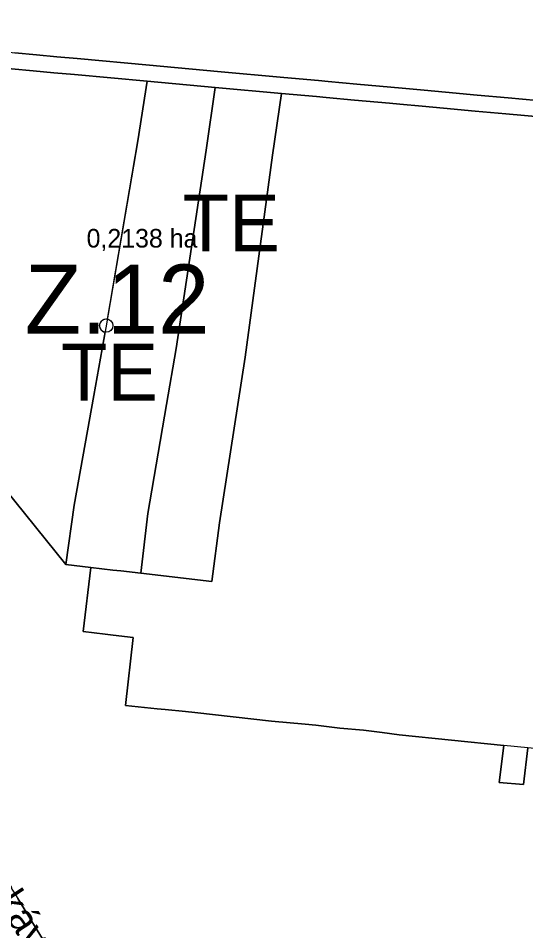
# Model space of a CAD drawing. Extents: x -555509 to -553005, y -1186756 to -1182560.
# Drawn here: x -554451.9 to -554326.9, y -1184312.3 to -1184087.6 of the extents above; entities that cross this region are included whole.
import ezdxf

# ---------------------------------------------------------------- set-up
doc = ezdxf.new("R2010")
doc.units = 0
for name, color, linetype in [('Level 15', 7, 'Continuous'), ('Level 26', 7, 'Continuous'), ('Level 29', 7, 'Continuous'), ('Level 36', 7, 'Continuous'), ('Level 4', 7, 'Continuous'), ('Level 46', 7, 'Continuous'), ('Level 52', 7, 'Continuous'), ('Level 56', 7, 'Continuous'), ('Level 57', 7, 'Continuous'), ('Level 59', 7, 'Continuous'), ('Level 6', 7, 'Continuous'), ('Level 63', 7, 'Continuous'), ('navrh_TE', 7, 'Continuous'), ('OBRYS_PLOCH', 7, 'Continuous'), ('stav_AP', 7, 'Continuous'), ('stav_BV', 7, 'Continuous'), ('stav_PU', 7, 'Continuous'), ('stav_TE', 7, 'Continuous'), ('stav_ZZ', 7, 'Continuous')]:
    doc.layers.add(name, color=color, linetype=linetype)

msp = doc.modelspace()

# ---------------------------------------------------------------- linework, layer by layer
at = {"layer": 'Level 15'}
msp.add_lwpolyline([(-554445.21, -1184315.42), (-554448.55, -1184310.07), (-554449.49, -1184308.45), (-554452.02, -1184304.43)], dxfattribs=at)
at = {"layer": 'Level 26'}
for p, q in [((-554448.17, -1184100.51), (-554443.1, -1184100.97)), ((-554376.06, -1184107.07), (-554369.02, -1184107.71)), ((-554369.02, -1184107.71), (-554360.47, -1184108.49)), ((-554331.76, -1184111.1), (-554321.21, -1184112.07))]:
    msp.add_line(p, q, dxfattribs=at)
for points in [[(-554368.51, -1184103.78), (-554375.53, -1184103.14), (-554377.89, -1184102.92), (-554386.44, -1184102.14), (-554402.8, -1184100.65), (-554419.51, -1184099.13), (-554437.34, -1184097.5), (-554442.37, -1184097.04), (-554447.41, -1184096.58), (-554452.71, -1184096.1)], [(-554464.64, -1184098.73), (-554453.5, -1184100.02), (-554448.17, -1184100.51)], [(-554443.1, -1184100.97), (-554438.03, -1184101.43), (-554420.12, -1184103.06), (-554403.37, -1184104.58), (-554387.01, -1184106.07), (-554378.42, -1184106.86), (-554376.06, -1184107.07)], [(-554165.91, -1184122.25), (-554184.57, -1184120.55), (-554194.22, -1184119.67), (-554204.27, -1184118.75), (-554209.96, -1184118.23), (-554215.7, -1184117.71), (-554222.5, -1184117.09), (-554230.67, -1184116.35), (-554238.72, -1184115.61), (-554251.02, -1184114.49), (-554269.76, -1184112.78), (-554288.18, -1184111.1), (-554294.43, -1184110.53), (-554300.68, -1184109.96), (-554310.42, -1184109.07), (-554315.86, -1184108.58), (-554320.66, -1184108.14), (-554331.2, -1184107.18), (-554338.84, -1184106.48), (-554346.65, -1184105.77), (-554351.87, -1184105.29), (-554357.35, -1184104.79), (-554368.51, -1184103.78)], [(-554360.47, -1184108.49), (-554357.89, -1184108.73), (-554352.39, -1184109.23)], [(-554352.39, -1184109.23), (-554347.18, -1184109.7), (-554339.38, -1184110.41), (-554331.76, -1184111.1)]]:
    msp.add_lwpolyline(points, dxfattribs=at)
at = {"layer": 'Level 36'}
msp.add_line((-554434.03, -1184222.84), (-554440.16, -1184222.12), dxfattribs=at)
for points in [[(-554440.16, -1184222.12), (-554492.51, -1184157.13), (-554513.37, -1184150.34), (-554518.87, -1184169.02), (-554521.24, -1184177.54), (-554523.13, -1184182.45), (-554525.77, -1184189.28)], [(-554283.1, -1184235.02), (-554284, -1184242.55), (-554283.44, -1184250.8), (-554287.72, -1184271.23), (-554326.33, -1184267.32), (-554332.24, -1184266.72), (-554358.07, -1184264.1), (-554362.22, -1184263.55), (-554366.82, -1184262.94), (-554372.66, -1184262.44), (-554378.6, -1184261.72), (-554381.18, -1184261.48), (-554389.53, -1184260.75), (-554408.36, -1184258.58), (-554410.7, -1184258.35), (-554415.69, -1184257.85), (-554417.69, -1184257.65), (-554425.5, -1184256.87), (-554423.54, -1184240.08), (-554428.47, -1184239.51), (-554430.45, -1184239.27), (-554435.88, -1184238.64), (-554434.03, -1184222.84)]]:
    msp.add_lwpolyline(points, dxfattribs=at)
at = {"layer": 'Level 4'}
msp.add_circle((-554430.21, -1184163.28), 1.64, dxfattribs=at)
at = {"layer": 'Level 52'}
for points in [[(-554419.97, -1184209.57), (-554421.69, -1184224.28), (-554404.2, -1184226.28), (-554402.34, -1184211.82), (-554397.8, -1184182.71), (-554395.98, -1184171.07), (-554389.22, -1184121.26), (-554387.01, -1184106.07), (-554403.37, -1184104.58), (-554405.62, -1184120.08), (-554413.02, -1184168.92), (-554415.38, -1184182.72), (-554419.97, -1184209.57)], [(-554326.33, -1184267.32), (-554327.43, -1184276.33), (-554333.44, -1184275.83), (-554332.24, -1184266.72), (-554358.07, -1184264.1), (-554362.22, -1184263.55), (-554366.82, -1184262.94), (-554372.66, -1184262.44), (-554378.6, -1184261.72), (-554381.18, -1184261.48), (-554389.53, -1184260.75), (-554408.36, -1184258.58), (-554410.7, -1184258.35), (-554415.69, -1184257.85), (-554417.69, -1184257.65), (-554425.5, -1184256.87), (-554423.54, -1184240.08), (-554428.47, -1184239.51), (-554430.45, -1184239.27), (-554435.88, -1184238.64), (-554434.03, -1184222.84), (-554440.16, -1184222.12), (-554492.51, -1184157.13)]]:
    msp.add_lwpolyline(points, dxfattribs=at)
at = {"layer": 'Level 56'}
for p, q in [((-554403.37, -1184104.58), (-554420.12, -1184103.06)), ((-554405.62, -1184120.08), (-554403.37, -1184104.58)), ((-554413.02, -1184168.92), (-554405.62, -1184120.08)), ((-554415.38, -1184182.72), (-554413.02, -1184168.92)), ((-554419.97, -1184209.57), (-554415.38, -1184182.72)), ((-554421.69, -1184224.28), (-554419.97, -1184209.57)), ((-554434.03, -1184222.84), (-554428.6, -1184223.48)), ((-554428.6, -1184223.48), (-554426.63, -1184223.71)), ((-554426.63, -1184223.71), (-554421.69, -1184224.28))]:
    msp.add_line(p, q, dxfattribs=at)
msp.add_lwpolyline([(-554420.12, -1184103.06), (-554422.41, -1184117.71), (-554430.77, -1184166.73), (-554433.24, -1184180.51), (-554438.09, -1184207.49), (-554440.16, -1184222.12), (-554434.03, -1184222.84)], dxfattribs=at)
at = {"layer": 'Level 6'}
msp.add_lwpolyline([(-554326.33, -1184267.32), (-554327.43, -1184276.33), (-554333.44, -1184275.83), (-554332.24, -1184266.72), (-554358.07, -1184264.1), (-554362.22, -1184263.55), (-554366.82, -1184262.94), (-554372.66, -1184262.44), (-554378.6, -1184261.72), (-554381.18, -1184261.48), (-554389.53, -1184260.75), (-554408.36, -1184258.58), (-554410.7, -1184258.35), (-554415.69, -1184257.85), (-554417.69, -1184257.65), (-554425.5, -1184256.87), (-554423.54, -1184240.08), (-554428.47, -1184239.51), (-554430.45, -1184239.27), (-554435.88, -1184238.64), (-554434.03, -1184222.84), (-554440.16, -1184222.12), (-554492.51, -1184157.13)], dxfattribs=at)
at = {"layer": 'navrh_TE'}
for p, q in [((-554403.37, -1184104.58), (-554420.12, -1184103.06)), ((-554403.37, -1184104.58), (-554420.12, -1184103.06)), ((-554405.62, -1184120.08), (-554403.37, -1184104.58)), ((-554405.62, -1184120.08), (-554403.37, -1184104.58)), ((-554413.02, -1184168.92), (-554405.62, -1184120.08)), ((-554413.02, -1184168.92), (-554405.62, -1184120.08)), ((-554415.38, -1184182.72), (-554413.02, -1184168.92)), ((-554415.38, -1184182.72), (-554413.02, -1184168.92)), ((-554419.97, -1184209.57), (-554415.38, -1184182.72)), ((-554419.97, -1184209.57), (-554415.38, -1184182.72)), ((-554421.69, -1184224.28), (-554419.97, -1184209.57)), ((-554421.69, -1184224.28), (-554419.97, -1184209.57)), ((-554434.03, -1184222.84), (-554428.6, -1184223.48)), ((-554434.03, -1184222.84), (-554428.6, -1184223.48)), ((-554428.6, -1184223.48), (-554426.63, -1184223.71)), ((-554428.6, -1184223.48), (-554426.63, -1184223.71)), ((-554426.63, -1184223.71), (-554421.69, -1184224.28)), ((-554426.63, -1184223.71), (-554421.69, -1184224.28))]:
    msp.add_line(p, q, dxfattribs=at)
msp.add_lwpolyline([(-554420.12, -1184103.06), (-554422.41, -1184117.71), (-554430.77, -1184166.73), (-554433.24, -1184180.51), (-554438.09, -1184207.49), (-554440.16, -1184222.12), (-554434.03, -1184222.84)], dxfattribs=at)
msp.add_lwpolyline([(-554420.12, -1184103.06), (-554422.41, -1184117.71), (-554430.77, -1184166.73), (-554433.24, -1184180.51), (-554438.09, -1184207.49), (-554440.16, -1184222.12), (-554434.03, -1184222.84)], dxfattribs=at)
at = {"layer": 'OBRYS_PLOCH'}
for p, q in [((-554448.17, -1184100.51), (-554443.1, -1184100.97)), ((-554403.37, -1184104.58), (-554420.12, -1184103.06)), ((-554405.62, -1184120.08), (-554403.37, -1184104.58)), ((-554387.01, -1184106.07), (-554389.22, -1184121.26)), ((-554376.06, -1184107.07), (-554369.02, -1184107.71)), ((-554369.02, -1184107.71), (-554376.06, -1184107.07)), ((-554369.02, -1184107.71), (-554360.47, -1184108.49)), ((-554360.47, -1184108.49), (-554369.02, -1184107.71)), ((-554357.89, -1184108.73), (-554360.47, -1184108.49)), ((-554352.39, -1184109.23), (-554357.89, -1184108.73)), ((-554347.18, -1184109.7), (-554352.39, -1184109.23)), ((-554339.38, -1184110.41), (-554347.18, -1184109.7)), ((-554331.76, -1184111.1), (-554339.38, -1184110.41)), ((-554331.76, -1184111.1), (-554321.21, -1184112.07)), ((-554321.21, -1184112.07), (-554331.76, -1184111.1)), ((-554413.02, -1184168.92), (-554405.62, -1184120.08)), ((-554389.22, -1184121.26), (-554395.98, -1184171.07)), ((-554415.38, -1184182.72), (-554413.02, -1184168.92)), ((-554395.98, -1184171.07), (-554397.8, -1184182.71)), ((-554419.97, -1184209.57), (-554415.38, -1184182.72)), ((-554397.8, -1184182.71), (-554402.34, -1184211.82)), ((-554421.69, -1184224.28), (-554419.97, -1184209.57)), ((-554402.34, -1184211.82), (-554404.2, -1184226.28)), ((-554434.03, -1184222.84), (-554440.16, -1184222.12)), ((-554434.03, -1184222.84), (-554435.88, -1184238.64)), ((-554434.03, -1184222.84), (-554428.6, -1184223.48)), ((-554428.6, -1184223.48), (-554434.03, -1184222.84)), ((-554428.6, -1184223.48), (-554426.63, -1184223.71)), ((-554426.63, -1184223.71), (-554428.6, -1184223.48)), ((-554426.63, -1184223.71), (-554421.69, -1184224.28)), ((-554421.69, -1184224.28), (-554426.63, -1184223.71)), ((-554404.2, -1184226.28), (-554421.69, -1184224.28)), ((-554435.88, -1184238.64), (-554430.45, -1184239.27)), ((-554428.47, -1184239.51), (-554430.45, -1184239.27)), ((-554430.45, -1184239.27), (-554428.47, -1184239.51)), ((-554423.54, -1184240.08), (-554428.47, -1184239.51)), ((-554428.47, -1184239.51), (-554423.54, -1184240.08)), ((-554425.5, -1184256.87), (-554423.54, -1184240.08)), ((-554423.54, -1184240.08), (-554425.5, -1184256.87)), ((-554417.69, -1184257.65), (-554425.5, -1184256.87)), ((-554415.69, -1184257.85), (-554417.69, -1184257.65)), ((-554410.7, -1184258.35), (-554415.69, -1184257.85)), ((-554415.69, -1184257.85), (-554410.7, -1184258.35)), ((-554408.36, -1184258.58), (-554410.7, -1184258.35)), ((-554410.7, -1184258.35), (-554408.36, -1184258.58)), ((-554378.6, -1184261.72), (-554381.18, -1184261.48)), ((-554381.18, -1184261.48), (-554378.6, -1184261.72)), ((-554372.66, -1184262.44), (-554378.6, -1184261.72)), ((-554378.6, -1184261.72), (-554372.66, -1184262.44)), ((-554366.82, -1184262.94), (-554372.66, -1184262.44)), ((-554372.66, -1184262.44), (-554366.82, -1184262.94)), ((-554362.22, -1184263.55), (-554366.82, -1184262.94)), ((-554366.82, -1184262.94), (-554362.22, -1184263.55)), ((-554358.07, -1184264.1), (-554362.22, -1184263.55)), ((-554362.22, -1184263.55), (-554358.07, -1184264.1)), ((-554332.24, -1184266.72), (-554358.07, -1184264.1)), ((-554358.07, -1184264.1), (-554332.24, -1184266.72)), ((-554333.44, -1184275.83), (-554332.24, -1184266.72)), ((-554332.24, -1184266.72), (-554333.44, -1184275.83)), ((-554326.33, -1184267.32), (-554327.43, -1184276.33)), ((-554327.43, -1184276.33), (-554326.33, -1184267.32)), ((-554327.43, -1184276.33), (-554333.44, -1184275.83)), ((-554333.44, -1184275.83), (-554327.43, -1184276.33)), ((-554448.55, -1184310.07), (-554445.21, -1184315.42))]:
    msp.add_line(p, q, dxfattribs=at)
for points in [[(-554521.41, -1184087.55), (-554510.78, -1184088.88), (-554505.63, -1184089.52), (-554500.07, -1184090.21), (-554488.69, -1184091.62), (-554478.43, -1184092.9), (-554468.65, -1184094.12), (-554463.81, -1184094.72), (-554452.71, -1184096.1), (-554447.41, -1184096.58), (-554442.37, -1184097.04), (-554437.34, -1184097.5), (-554419.51, -1184099.13), (-554402.8, -1184100.65), (-554386.44, -1184102.14), (-554377.89, -1184102.92), (-554375.53, -1184103.14), (-554368.51, -1184103.78)], [(-554368.51, -1184103.78), (-554375.53, -1184103.14), (-554377.89, -1184102.92), (-554386.44, -1184102.14), (-554402.8, -1184100.65), (-554419.51, -1184099.13), (-554437.34, -1184097.5), (-554442.37, -1184097.04), (-554447.41, -1184096.58), (-554452.71, -1184096.1)], [(-554464.64, -1184098.73), (-554453.5, -1184100.02), (-554448.17, -1184100.51)], [(-554443.1, -1184100.97), (-554438.03, -1184101.43), (-554420.12, -1184103.06), (-554403.37, -1184104.58), (-554387.01, -1184106.07), (-554378.42, -1184106.86), (-554376.06, -1184107.07)], [(-554420.12, -1184103.06), (-554422.41, -1184117.71), (-554430.77, -1184166.73), (-554433.24, -1184180.51), (-554438.09, -1184207.49), (-554440.16, -1184222.12), (-554434.03, -1184222.84)], [(-554165.91, -1184122.25), (-554184.57, -1184120.55), (-554194.22, -1184119.67), (-554204.27, -1184118.75), (-554209.96, -1184118.23), (-554215.7, -1184117.71), (-554222.5, -1184117.09), (-554230.67, -1184116.35), (-554238.72, -1184115.61), (-554251.02, -1184114.49), (-554269.76, -1184112.78), (-554288.18, -1184111.1), (-554294.43, -1184110.53), (-554300.68, -1184109.96), (-554310.42, -1184109.07), (-554315.86, -1184108.58), (-554320.66, -1184108.14), (-554331.2, -1184107.18), (-554338.84, -1184106.48), (-554346.65, -1184105.77), (-554351.87, -1184105.29), (-554357.35, -1184104.79), (-554368.51, -1184103.78)], [(-554368.51, -1184103.78), (-554357.35, -1184104.79), (-554351.87, -1184105.29), (-554346.65, -1184105.77), (-554338.84, -1184106.48), (-554331.2, -1184107.18), (-554320.66, -1184108.14), (-554315.86, -1184108.58), (-554310.42, -1184109.07), (-554300.68, -1184109.96), (-554294.43, -1184110.53), (-554288.18, -1184111.1), (-554269.76, -1184112.78), (-554251.02, -1184114.49), (-554238.72, -1184115.61), (-554230.67, -1184116.35), (-554222.5, -1184117.09), (-554215.7, -1184117.71), (-554209.96, -1184118.23), (-554204.27, -1184118.75), (-554194.22, -1184119.67), (-554184.57, -1184120.55), (-554165.91, -1184122.25)], [(-554403.37, -1184104.58), (-554405.62, -1184120.08)], [(-554387.01, -1184106.07), (-554403.37, -1184104.58)], [(-554389.22, -1184121.26), (-554387.01, -1184106.07)], [(-554376.06, -1184107.07), (-554378.42, -1184106.86), (-554387.01, -1184106.07)], [(-554360.47, -1184108.49), (-554357.89, -1184108.73), (-554352.39, -1184109.23)], [(-554352.39, -1184109.23), (-554347.18, -1184109.7), (-554339.38, -1184110.41), (-554331.76, -1184111.1)], [(-554405.62, -1184120.08), (-554409.66, -1184146.74), (-554413.02, -1184168.92)], [(-554395.98, -1184171.07), (-554389.22, -1184121.26)], [(-554440.16, -1184222.12), (-554492.51, -1184157.13), (-554513.37, -1184150.34)], [(-554413.02, -1184168.92), (-554415.38, -1184182.72)], [(-554397.8, -1184182.71), (-554395.98, -1184171.07)], [(-554415.38, -1184182.72), (-554419.97, -1184209.57)], [(-554402.34, -1184211.82), (-554397.8, -1184182.71)], [(-554419.97, -1184209.57), (-554421.69, -1184224.28)], [(-554404.2, -1184226.28), (-554402.34, -1184211.82)], [(-554430.45, -1184239.27), (-554435.88, -1184238.64), (-554434.03, -1184222.84)], [(-554421.69, -1184224.28), (-554404.2, -1184226.28)], [(-554425.5, -1184256.87), (-554417.69, -1184257.65), (-554415.69, -1184257.85)], [(-554381.18, -1184261.48), (-554389.53, -1184260.75), (-554408.36, -1184258.58)], [(-554408.36, -1184258.58), (-554389.53, -1184260.75), (-554381.18, -1184261.48)], [(-554461.16, -1184290.15), (-554452.02, -1184304.43), (-554449.49, -1184308.45), (-554448.55, -1184310.07)]]:
    msp.add_lwpolyline(points, dxfattribs=at)
at = {"layer": 'stav_AP'}
for points in [[(-554521.41, -1184087.55), (-554510.78, -1184088.88), (-554505.63, -1184089.52), (-554500.07, -1184090.21), (-554488.69, -1184091.62), (-554478.43, -1184092.9), (-554468.65, -1184094.12), (-554463.81, -1184094.72), (-554452.71, -1184096.1), (-554447.41, -1184096.58), (-554442.37, -1184097.04), (-554437.34, -1184097.5), (-554419.51, -1184099.13), (-554402.8, -1184100.65), (-554386.44, -1184102.14), (-554377.89, -1184102.92), (-554375.53, -1184103.14), (-554368.51, -1184103.78)], [(-554368.51, -1184103.78), (-554357.35, -1184104.79), (-554351.87, -1184105.29), (-554346.65, -1184105.77), (-554338.84, -1184106.48), (-554331.2, -1184107.18), (-554320.66, -1184108.14), (-554315.86, -1184108.58), (-554310.42, -1184109.07), (-554300.68, -1184109.96), (-554294.43, -1184110.53), (-554288.18, -1184111.1), (-554269.76, -1184112.78), (-554251.02, -1184114.49), (-554238.72, -1184115.61), (-554230.67, -1184116.35), (-554222.5, -1184117.09), (-554215.7, -1184117.71), (-554209.96, -1184118.23), (-554204.27, -1184118.75), (-554194.22, -1184119.67), (-554184.57, -1184120.55), (-554165.91, -1184122.25)]]:
    msp.add_lwpolyline(points, dxfattribs=at)
at = {"layer": 'stav_BV'}
for p, q in [((-554440.16, -1184222.12), (-554492.51, -1184157.13)), ((-554434.03, -1184222.84), (-554440.16, -1184222.12)), ((-554423.54, -1184240.08), (-554428.47, -1184239.51)), ((-554425.5, -1184256.87), (-554423.54, -1184240.08)), ((-554362.22, -1184263.55), (-554366.82, -1184262.94)), ((-554358.07, -1184264.1), (-554362.22, -1184263.55)), ((-554332.24, -1184266.72), (-554358.07, -1184264.1)), ((-554333.44, -1184275.83), (-554332.24, -1184266.72)), ((-554326.33, -1184267.32), (-554327.43, -1184276.33)), ((-554327.43, -1184276.33), (-554333.44, -1184275.83))]:
    msp.add_line(p, q, dxfattribs=at)
for points in [[(-554428.47, -1184239.51), (-554430.45, -1184239.27), (-554435.88, -1184238.64), (-554434.03, -1184222.84)], [(-554389.53, -1184260.75), (-554408.36, -1184258.58), (-554410.7, -1184258.35), (-554415.69, -1184257.85), (-554417.69, -1184257.65), (-554425.5, -1184256.87)], [(-554378.6, -1184261.72), (-554381.18, -1184261.48), (-554389.53, -1184260.75)], [(-554366.82, -1184262.94), (-554372.66, -1184262.44), (-554378.6, -1184261.72)], [(-554452.02, -1184304.43), (-554449.49, -1184308.45), (-554448.55, -1184310.07), (-554445.21, -1184315.42)]]:
    msp.add_lwpolyline(points, dxfattribs=at)
at = {"layer": 'stav_PU'}
msp.add_lwpolyline([(-554445.21, -1184315.42), (-554448.55, -1184310.07), (-554449.49, -1184308.45), (-554452.02, -1184304.43)], dxfattribs=at)
at = {"layer": 'stav_TE'}
for points in [[(-554403.37, -1184104.58), (-554405.62, -1184120.08)], [(-554387.01, -1184106.07), (-554403.37, -1184104.58)], [(-554389.22, -1184121.26), (-554387.01, -1184106.07)], [(-554405.62, -1184120.08), (-554409.66, -1184146.74), (-554413.02, -1184168.92)], [(-554395.98, -1184171.07), (-554389.22, -1184121.26)], [(-554413.02, -1184168.92), (-554415.38, -1184182.72)], [(-554397.8, -1184182.71), (-554395.98, -1184171.07)], [(-554415.38, -1184182.72), (-554419.97, -1184209.57)], [(-554402.34, -1184211.82), (-554397.8, -1184182.71)], [(-554419.97, -1184209.57), (-554421.69, -1184224.28)], [(-554404.2, -1184226.28), (-554402.34, -1184211.82)], [(-554421.69, -1184224.28), (-554404.2, -1184226.28)]]:
    msp.add_lwpolyline(points, dxfattribs=at)
at = {"layer": 'stav_ZZ'}
for p, q in [((-554420.12, -1184103.06), (-554438.03, -1184101.43)), ((-554422.41, -1184117.71), (-554420.12, -1184103.06)), ((-554387.01, -1184106.07), (-554389.22, -1184121.26)), ((-554369.02, -1184107.71), (-554376.06, -1184107.07)), ((-554360.47, -1184108.49), (-554369.02, -1184107.71)), ((-554357.89, -1184108.73), (-554360.47, -1184108.49)), ((-554352.39, -1184109.23), (-554357.89, -1184108.73)), ((-554347.18, -1184109.7), (-554352.39, -1184109.23)), ((-554339.38, -1184110.41), (-554347.18, -1184109.7)), ((-554331.76, -1184111.1), (-554339.38, -1184110.41)), ((-554321.21, -1184112.07), (-554331.76, -1184111.1)), ((-554429.91, -1184161.67), (-554422.41, -1184117.71)), ((-554389.22, -1184121.26), (-554395.98, -1184171.07)), ((-554395.98, -1184171.07), (-554397.8, -1184182.71)), ((-554397.8, -1184182.71), (-554402.34, -1184211.82)), ((-554402.34, -1184211.82), (-554404.2, -1184226.28)), ((-554434.03, -1184222.84), (-554435.88, -1184238.64)), ((-554428.6, -1184223.48), (-554434.03, -1184222.84)), ((-554426.63, -1184223.71), (-554428.6, -1184223.48)), ((-554421.69, -1184224.28), (-554426.63, -1184223.71)), ((-554404.2, -1184226.28), (-554421.69, -1184224.28)), ((-554435.88, -1184238.64), (-554430.45, -1184239.27)), ((-554430.45, -1184239.27), (-554428.47, -1184239.51)), ((-554428.47, -1184239.51), (-554423.54, -1184240.08)), ((-554423.54, -1184240.08), (-554425.5, -1184256.87)), ((-554425.5, -1184256.87), (-554417.69, -1184257.65)), ((-554378.6, -1184261.72), (-554372.66, -1184262.44)), ((-554372.66, -1184262.44), (-554366.82, -1184262.94)), ((-554366.82, -1184262.94), (-554362.22, -1184263.55)), ((-554362.22, -1184263.55), (-554358.07, -1184264.1)), ((-554358.07, -1184264.1), (-554332.24, -1184266.72)), ((-554332.24, -1184266.72), (-554333.44, -1184275.83)), ((-554327.43, -1184276.33), (-554326.33, -1184267.32)), ((-554333.44, -1184275.83), (-554327.43, -1184276.33))]:
    msp.add_line(p, q, dxfattribs=at)
for points in [[(-554448.17, -1184100.51), (-554453.5, -1184100.02), (-554464.64, -1184098.73)], [(-554438.03, -1184101.43), (-554443.1, -1184100.97), (-554448.17, -1184100.51)], [(-554376.06, -1184107.07), (-554378.42, -1184106.86), (-554387.01, -1184106.07)], [(-554513.37, -1184150.34), (-554492.51, -1184157.13), (-554440.16, -1184222.12)], [(-554433.24, -1184180.51), (-554430.77, -1184166.73), (-554430.46, -1184164.9)], [(-554440.16, -1184222.12), (-554438.09, -1184207.49), (-554433.24, -1184180.51)], [(-554417.69, -1184257.65), (-554415.69, -1184257.85), (-554410.7, -1184258.35), (-554408.36, -1184258.58), (-554389.53, -1184260.75)], [(-554389.53, -1184260.75), (-554381.18, -1184261.48), (-554378.6, -1184261.72)]]:
    msp.add_lwpolyline(points, dxfattribs=at)
msp.add_arc((-554430.21, -1184163.28), 1.64, 79.4392, 261.2043, dxfattribs=at)

# ---------------------------------------------------------------- texts
at = {"layer": 'Level 29'}
msp.add_text('0,2138 ha', height=4.588, dxfattribs=at).set_placement((-554435.04, -1184144.04))
at = {"layer": 'Level 46'}
msp.add_text('Z.12', height=17, dxfattribs=at).set_placement((-554450.26, -1184165.22))
at = {"layer": 'Level 57'}
msp.add_text('Rukáv', height=7.174, rotation=303.3977, dxfattribs=at).set_placement((-554464.29, -1184295.01))
at = {"layer": 'Level 59'}
msp.add_text('TE', height=14, dxfattribs=at).set_placement((-554411.37, -1184144.98))
at = {"layer": 'Level 63'}
msp.add_text('TE', height=14, dxfattribs=at).set_placement((-554441.37, -1184181.74))

doc.saveas('drawing.dxf')
